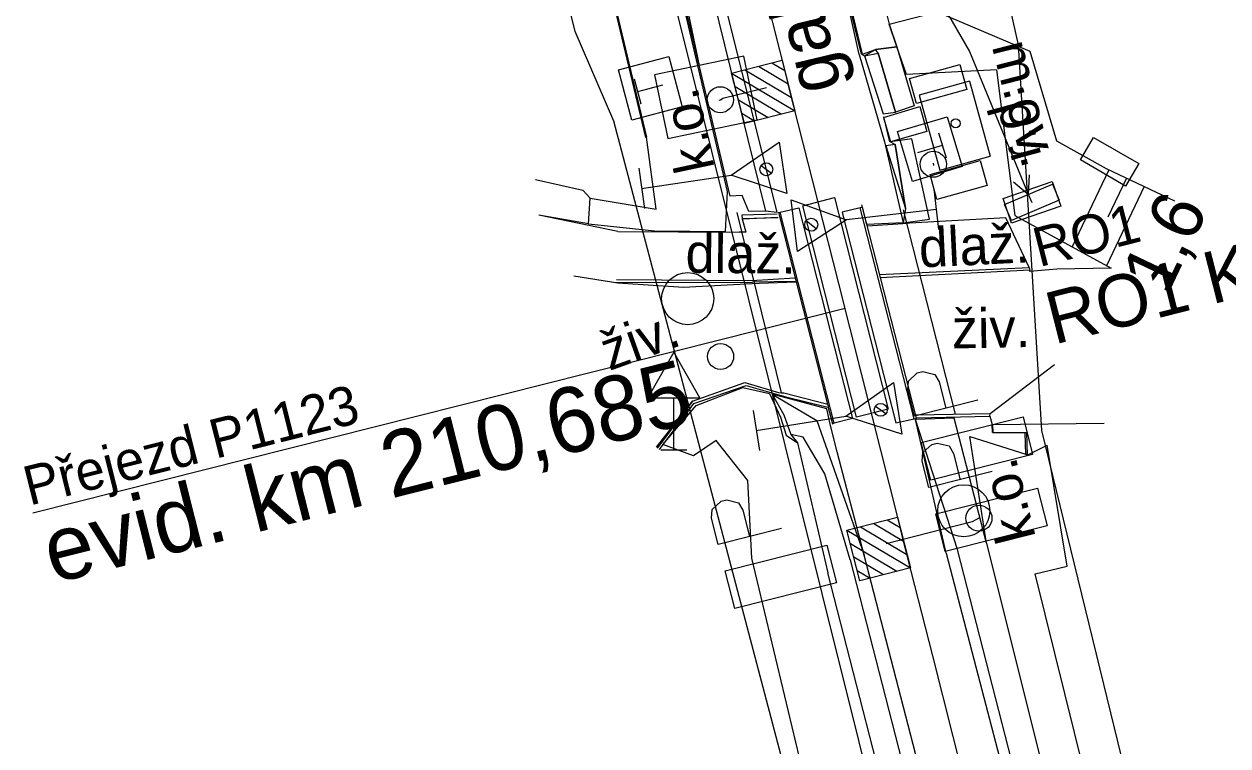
# Model space of a CAD drawing. Extents: x -754679 to -754173, y -1169241 to -1168288.
# Drawn here: x -754417.2 to -754371, y -1168972.24 to -1168944.54 of the extents above; entities that cross this region are included whole.
import ezdxf

# ---------------------------------------------------------------- set-up
doc = ezdxf.new("R2010")
doc.units = 0
for name, color, linetype in [('Vrstva 1', 7, 'Continuous'), ('Vrstva 13', 7, 'Continuous'), ('Vrstva 16', 7, 'Continuous'), ('Vrstva 23', 7, 'Continuous'), ('Vrstva 25', 7, 'Continuous'), ('Vrstva 27', 7, 'Continuous'), ('Vrstva 3', 7, 'Continuous'), ('Vrstva 31', 7, 'Continuous'), ('Vrstva 33', 7, 'Continuous'), ('Vrstva 37', 7, 'Continuous'), ('Vrstva 4', 7, 'Continuous'), ('Vrstva 43', 7, 'Continuous'), ('Vrstva 48', 7, 'Continuous'), ('Vrstva 49', 7, 'Continuous'), ('Vrstva 51', 7, 'Continuous'), ('Vrstva 53', 7, 'Continuous'), ('Vrstva 59', 7, 'Continuous'), ('Vrstva 63', 7, 'Continuous'), ('Vrstva 7', 7, 'Continuous')]:
    doc.layers.add(name, color=color, linetype=linetype)

msp = doc.modelspace()

# ---------------------------------------------------------------- linework, layer by layer
at = {"layer": 'Vrstva 1'}
for points in [[(-754384.656, -1168959.571), (-754385.936, -1168954.491), (-754386.734, -1168951.322), (-754387.865, -1168946.893), (-754387.928, -1168946.598), (-754389.016, -1168942.293), (-754391.2, -1168933.67), (-754393.647, -1168923.979), (-754396.084, -1168914.315), (-754398.294, -1168905.574)], [(-754382.327, -1168968.778), (-754383.436, -1168964.432), (-754383.656, -1168963.522), (-754384.656, -1168959.571)], [(-754371.756, -1169010.617), (-754373.805, -1169002.503), (-754376.012, -1168993.767), (-754377.617, -1168987.413), (-754379.98, -1168978.062), (-754382.327, -1168968.778)]]:
    msp.add_lwpolyline(points, dxfattribs=at)
at = {"layer": 'Vrstva 13'}
for p, q in [((-754385.032, -1168945.69), (-754385.963, -1168941.8)), ((-754384.759, -1168941.493), (-754384.006, -1168944.538)), ((-754385.064, -1168945.684), (-754386.023, -1168941.847)), ((-754385.032, -1168945.69), (-754384.522, -1168945.516)), ((-754385.064, -1168945.684), (-754385.032, -1168945.69)), ((-754375.751, -1168959.859), (-754380.036, -1168959.915)), ((-754380.025, -1168960.213), (-754378.726, -1168960.213)), ((-754378.753, -1168961.045), (-754378.786, -1168960.228)), ((-754378.726, -1168960.213), (-754378.701, -1168961.079)), ((-754378.701, -1168961.079), (-754378.753, -1168961.045))]:
    msp.add_line(p, q, dxfattribs=at)
for points in [[(-754384.006, -1168944.538), (-754383.71, -1168945.407), (-754384.522, -1168945.516)], [(-754385.064, -1168945.684), (-754384.955, -1168945.759), (-754384.522, -1168945.516)], [(-754378.726, -1168960.213), (-754378.786, -1168960.228), (-754380.038, -1168960.207), (-754380.043, -1168959.901), (-754380.036, -1168959.915)], [(-754380.036, -1168959.915), (-754380.025, -1168960.213), (-754380.038, -1168960.207)]]:
    msp.add_lwpolyline(points, dxfattribs=at)
at = {"layer": 'Vrstva 16'}
for p, q in [((-754390.209, -1168950.962), (-754395.222, -1168929.578)), ((-754397.82, -1168929.888), (-754393.322, -1168948.872)), ((-754384.955, -1168945.759), (-754384.428, -1168945.654)), ((-754384.428, -1168945.654), (-754383.763, -1168947.919)), ((-754395.546, -1168952.201), (-754395.477, -1168951.215)), ((-754391.51, -1168961.104), (-754392.688, -1168960.67)), ((-754377.17, -1168965.333), (-754377.937, -1168960.698)), ((-754380.262, -1168964.46), (-754374.593, -1168987.21)), ((-754383.092, -1168990.79), (-754389.273, -1168965.032)), ((-754378.402, -1168965.63), (-754377.17, -1168965.333)), ((-754380.395, -1168988.747), (-754386.358, -1168965.597)), ((-754373.145, -1168986.727), (-754378.402, -1168965.63))]:
    msp.add_line(p, q, dxfattribs=at)
for points in [[(-754384.955, -1168945.759), (-754384.237, -1168947.982), (-754383.763, -1168947.919)], [(-754395.477, -1168951.215), (-754392.947, -1168951.633), (-754393.322, -1168948.872)], [(-754383.768, -1168949.156), (-754384.136, -1168949.206), (-754383.375, -1168951.611), (-754383.768, -1168949.156)], [(-754395.546, -1168952.201), (-754393.01, -1168952.466), (-754390.289, -1168952.493), (-754390.209, -1168950.962)], [(-754392.688, -1168960.67), (-754391.408, -1168959.175), (-754389.621, -1168958.478), (-754388.593, -1168958.711), (-754388.173, -1168959.62), (-754387.958, -1168960.306), (-754387.518, -1168960.602), (-754386.358, -1168965.597)], [(-754389.273, -1168965.032), (-754389.425, -1168962.053), (-754390.641, -1168960.512), (-754391.51, -1168961.104)], [(-754380.262, -1168964.46), (-754380.906, -1168960.36), (-754378.753, -1168961.045), (-754378.701, -1168961.079), (-754377.937, -1168960.698)]]:
    msp.add_lwpolyline(points, dxfattribs=at)
at = {"layer": 'Vrstva 23'}
for p, q in [((-754380.917, -1168946.723), (-754382.852, -1168947.261)), ((-754380.917, -1168946.723), (-754380.127, -1168949.604)), ((-754382.852, -1168947.261), (-754382.062, -1168950.142)), ((-754384.221, -1168948.119), (-754382.823, -1168947.697)), ((-754382.062, -1168950.142), (-754380.127, -1168949.604))]:
    msp.add_line(p, q, dxfattribs=at)
for points in [[(-754393.344, -1168948.888), (-754397.546, -1168931.205), (-754401.742, -1168913.695), (-754408.583, -1168884.482)], [(-754382.823, -1168947.697), (-754382.557, -1168948.653), (-754383.948, -1168949.058), (-754383.977, -1168949.056), (-754384.212, -1168948.093), (-754384.221, -1168948.119), (-754383.948, -1168949.058)]]:
    msp.add_lwpolyline(points, dxfattribs=at)
at = {"layer": 'Vrstva 25'}
for points in [[(-754385.337, -1168937.932), (-754380.924, -1168945.594), (-754378.67, -1168951.057), (-754378.525, -1168951.376)], [(-754381.29, -1168946.084), (-754381.023, -1168947.048), (-754382.95, -1168947.584), (-754383.217, -1168946.62), (-754381.29, -1168946.084)], [(-754376.658, -1168949.746), (-754376.155, -1168948.882), (-754374.426, -1168949.888), (-754374.929, -1168950.752), (-754376.658, -1168949.746)], [(-754382.167, -1168951.272), (-754382.434, -1168950.308), (-754380.507, -1168949.772), (-754380.24, -1168950.736), (-754382.167, -1168951.272)], [(-754379.308, -1168952.174), (-754379.633, -1168951.228), (-754377.742, -1168950.578), (-754377.417, -1168951.524), (-754379.308, -1168952.174)]]:
    msp.add_lwpolyline(points, dxfattribs=at)
at = {"layer": 'Vrstva 27'}
for p, q in [((-754390.53, -1168947.452), (-754390.434, -1168947.426)), ((-754382.319, -1168949.867), (-754382.295, -1168949.963)), ((-754380.605, -1168963.514), (-754380.511, -1168963.48))]:
    msp.add_line(p, q, dxfattribs=at)
for points in [[(-754390.482, -1168947.439), (-754390.388, -1168947.376), (-754388.713, -1168946.964)], [(-754380.558, -1168963.497), (-754380.816, -1168963.643), (-754384.119, -1168964.483)]]:
    msp.add_lwpolyline(points, dxfattribs=at)
for centre in [(-754390.482, -1168947.439), (-754382.307, -1168949.915), (-754380.558, -1168963.497)]:
    msp.add_circle(centre, 0.5, dxfattribs=at)
at = {"layer": 'Vrstva 3'}
for p, q in [((-754390.05, -1168946.419), (-754387.618, -1168947.862)), ((-754389.537, -1168946.288), (-754387.749, -1168947.348)), ((-754389.022, -1168946.156), (-754387.88, -1168946.834)), ((-754388.509, -1168946.025), (-754388.011, -1168946.32)), ((-754389.919, -1168946.932), (-754388.131, -1168947.993)), ((-754389.788, -1168947.447), (-754388.646, -1168948.124)), ((-754389.657, -1168947.96), (-754389.159, -1168948.256)), ((-754385.621, -1168963.958), (-754383.189, -1168965.401)), ((-754385.108, -1168963.827), (-754383.32, -1168964.887)), ((-754384.593, -1168963.695), (-754383.451, -1168964.373)), ((-754384.08, -1168963.564), (-754383.582, -1168963.859)), ((-754385.49, -1168964.471), (-754383.702, -1168965.532)), ((-754385.359, -1168964.986), (-754384.217, -1168965.663)), ((-754385.228, -1168965.499), (-754384.73, -1168965.794))]:
    msp.add_line(p, q, dxfattribs=at)
for points in [[(-754388.112, -1168945.924), (-754387.618, -1168947.862), (-754389.555, -1168948.357), (-754390.05, -1168946.419)], [(-754383.683, -1168963.463), (-754383.189, -1168965.401), (-754385.127, -1168965.895), (-754385.621, -1168963.958)]]:
    msp.add_lwpolyline(points, close=True, dxfattribs=at)
at = {"layer": 'Vrstva 31'}
msp.add_lwpolyline([(-754388.719, -1168923.201), (-754385.337, -1168937.932), (-754380.924, -1168945.594), (-754378.67, -1168951.057), (-754378.525, -1168951.376)], dxfattribs=at)
at = {"layer": 'Vrstva 33'}
for p, q in [((-754393.523, -1168947.612), (-754393.778, -1168946.645)), ((-754393.65, -1168947.129), (-754392.684, -1168946.873)), ((-754382.106, -1168948.711), (-754381.818, -1168949.669)), ((-754381.962, -1168949.19), (-754382.92, -1168949.478)), ((-754379.573, -1168951.471), (-754379.569, -1168951.463))]:
    msp.add_line(p, q, dxfattribs=at)
for points in [[(-754393.879, -1168948.223), (-754394.389, -1168946.289), (-754392.455, -1168945.779), (-754391.945, -1168947.713), (-754393.879, -1168948.223)], [(-754381.771, -1168948.089), (-754381.196, -1168950.004), (-754383.111, -1168950.579), (-754383.686, -1168948.664), (-754381.771, -1168948.089)], [(-754379.227, -1168950.589), (-754378.657, -1168951.07), (-754378.614, -1168950.326)], [(-754383.287, -1168958.57), (-754383.262, -1168958.238), (-754382.923, -1168957.924), (-754382.708, -1168957.87), (-754382.251, -1168957.983), (-754382.087, -1168958.267)], [(-754382.087, -1168958.267), (-754381.832, -1168959.278)], [(-754383.032, -1168959.581), (-754383.287, -1168958.57)], [(-754380.6, -1168958.968), (-754383.032, -1168959.581)], [(-754382.732, -1168961.313), (-754382.708, -1168960.981), (-754382.368, -1168960.667), (-754382.154, -1168960.613), (-754381.697, -1168960.726), (-754381.532, -1168961.01)], [(-754381.532, -1168961.01), (-754381.277, -1168962.021)], [(-754382.477, -1168962.324), (-754382.732, -1168961.313)], [(-754380.045, -1168961.71), (-754382.477, -1168962.324)], [(-754390.816, -1168963.496), (-754390.792, -1168963.164), (-754390.452, -1168962.85), (-754390.238, -1168962.796), (-754389.781, -1168962.909), (-754389.616, -1168963.193)], [(-754390.561, -1168964.507), (-754390.816, -1168963.496)], [(-754389.616, -1168963.193), (-754389.361, -1168964.204)], [(-754388.129, -1168963.893), (-754390.561, -1168964.507)]]:
    msp.add_lwpolyline(points, dxfattribs=at)
for points in [[(-754379.575, -1168951.465), (-754377.738, -1168950.674), (-754377.475, -1168951.287), (-754379.312, -1168952.078)], [(-754382.404, -1168962.035), (-754382.768, -1168960.591), (-754378.861, -1168959.607), (-754378.498, -1168961.051)], [(-754381.848, -1168964.778), (-754382.212, -1168963.334), (-754378.306, -1168962.348), (-754377.941, -1168963.791)], [(-754389.932, -1168966.961), (-754390.296, -1168965.517), (-754386.39, -1168964.531), (-754386.025, -1168965.974)]]:
    msp.add_lwpolyline(points, close=True, dxfattribs=at)
at = {"layer": 'Vrstva 37'}
msp.add_circle((-754390.471, -1168957.291), 0.5, dxfattribs=at)
at = {"layer": 'Vrstva 4'}
for p, q in [((-754395.222, -1168929.578), (-754390.121, -1168951.135)), ((-754394.179, -1168929.708), (-754388.744, -1168951.72)), ((-754388.295, -1168951.767), (-754393.809, -1168929.698)), ((-754385.154, -1168945.699), (-754386.014, -1168941.847)), ((-754385.154, -1168945.699), (-754384.183, -1168949.051)), ((-754393.613, -1168950.071), (-754393.391, -1168951.611)), ((-754388.912, -1168949.959), (-754388.521, -1168950.254)), ((-754382.102, -1168952.423), (-754382.276, -1168950.877)), ((-754388.744, -1168951.72), (-754389.386, -1168951.727)), ((-754388.295, -1168951.767), (-754388.744, -1168951.72)), ((-754388.251, -1168951.769), (-754388.18, -1168951.751)), ((-754386.804, -1168952.39), (-754387.185, -1168952.083)), ((-754385.695, -1168955.447), (-754416.868, -1168963.298)), ((-754386.398, -1168959.295), (-754388.488, -1168958.734)), ((-754388.488, -1168958.734), (-754388.043, -1168959.526)), ((-754389.221, -1168959.358), (-754388.983, -1168960.896)), ((-754384.522, -1168959.194), (-754384.128, -1168959.484)), ((-754388.043, -1168959.526), (-754387.779, -1168960.28)), ((-754383.049, -1168959.681), (-754382.957, -1168959.657)), ((-754381.503, -1168959.659), (-754382.994, -1168959.713)), ((-754381.376, -1168964.701), (-754382.994, -1168959.713)), ((-754381.816, -1168964.835), (-754382.994, -1168959.713)), ((-754380.262, -1168964.46), (-754381.503, -1168959.659)), ((-754386.178, -1168959.871), (-754386.113, -1168959.854)), ((-754384.968, -1168964.915), (-754385.997, -1168960.947)), ((-754385.501, -1168965.091), (-754386.471, -1168961.789)), ((-754380.262, -1168964.46), (-754374.593, -1168987.21)), ((-754378.902, -1168988.336), (-754384.968, -1168964.915)), ((-754381.816, -1168964.835), (-754375.862, -1168987.584)), ((-754375.554, -1168987.357), (-754381.376, -1168964.701)), ((-754385.501, -1168965.091), (-754379.508, -1168988.473)), ((-754380.395, -1168988.747), (-754386.358, -1168965.597))]:
    msp.add_line(p, q, dxfattribs=at)
for points in [[(-754383.71, -1168945.407), (-754383.049, -1168947.673), (-754383.763, -1168947.919), (-754384.428, -1168945.654), (-754384.522, -1168945.516), (-754383.71, -1168945.407)], [(-754393.502, -1168950.841), (-754390.062, -1168950.335), (-754388.221, -1168949.067), (-754387.924, -1168951.043), (-754390.062, -1168950.335)], [(-754384.183, -1168949.051), (-754383.468, -1168952.159), (-754384.853, -1168952.232), (-754385.049, -1168951.469)], [(-754383.468, -1168952.159), (-754382.456, -1168952.028), (-754383.132, -1168948.942), (-754383.948, -1168949.058), (-754383.768, -1168949.156), (-754383.375, -1168951.611), (-754383.468, -1168952.159)], [(-754389.386, -1168951.727), (-754389.648, -1168951.116), (-754390.121, -1168951.135)], [(-754382.189, -1168951.65), (-754385.643, -1168952.05), (-754387.522, -1168953.26), (-754387.758, -1168951.276), (-754385.643, -1168952.05)], [(-754384.042, -1168959.317), (-754385.257, -1168959.617), (-754387.319, -1168951.515), (-754386.094, -1168951.188), (-754384.042, -1168959.317)], [(-754388.251, -1168951.769), (-754388.199, -1168951.972), (-754387.569, -1168954.421), (-754386.369, -1168959.123), (-754386.343, -1168959.225), (-754386.338, -1168959.246), (-754386.178, -1168959.871)], [(-754385.407, -1168959.668), (-754386.113, -1168959.854), (-754388.18, -1168951.751), (-754387.468, -1168951.586), (-754385.407, -1168959.668)], [(-754383.749, -1168959.835), (-754383.049, -1168959.681), (-754385.116, -1168951.584), (-754385.803, -1168951.759), (-754385.802, -1168951.762), (-754383.749, -1168959.835)], [(-754385.02, -1168951.56), (-754385.116, -1168951.584)], [(-754382.957, -1168959.657), (-754385.02, -1168951.56)], [(-754389.102, -1168960.127), (-754385.668, -1168959.583), (-754383.841, -1168958.294), (-754383.522, -1168960.267), (-754385.668, -1168959.583)], [(-754388.488, -1168958.734), (-754386.775, -1168959.754), (-754384.968, -1168964.915)], [(-754385.997, -1168960.947), (-754386.261, -1168959.886), (-754386.398, -1168959.295)], [(-754386.471, -1168961.789), (-754387.297, -1168960.39), (-754387.779, -1168960.28)], [(-754387.779, -1168960.28), (-754387.518, -1168960.602), (-754386.358, -1168965.597)]]:
    msp.add_lwpolyline(points, dxfattribs=at)
for centre in [(-754388.718, -1168950.107), (-754386.994, -1168952.236), (-754384.326, -1168959.34)]:
    msp.add_circle(centre, 0.248, dxfattribs=at)
at = {"layer": 'Vrstva 43'}
for p, q in [((-754388.13, -1168958.682), (-754389.832, -1168951.766)), ((-754381.456, -1168959.502), (-754383.446, -1168951.67))]:
    msp.add_line(p, q, dxfattribs=at)
for centre in [(-754391.734, -1168955.072), (-754381.14, -1168963.213)]:
    msp.add_circle(centre, 1, dxfattribs=at)
at = {"layer": 'Vrstva 48'}
for p, q in [((-754375.576, -1168950.125), (-754376.982, -1168953.083)), ((-754374.899, -1168950.446), (-754375.611, -1168951.946)), ((-754374.221, -1168950.768), (-754375.666, -1168953.808))]:
    msp.add_line(p, q, dxfattribs=at)
at = {"layer": 'Vrstva 49'}
for points in [[(-754384.006, -1168944.538), (-754382.158, -1168944.067), (-754378.6, -1168945.58), (-754377.58, -1168949.01), (-754375.672, -1168950.079), (-754373.052, -1168951.324)], [(-754379.885, -1168946.291), (-754383.334, -1168946.469), (-754383.71, -1168945.407), (-754384.006, -1168944.538)], [(-754379.885, -1168946.291), (-754379.174, -1168951.877), (-754375.483, -1168953.908)], [(-754397.582, -1168950.504), (-754395.757, -1168950.913), (-754395.477, -1168951.215)], [(-754395.546, -1168952.201), (-754397.45, -1168951.868)]]:
    msp.add_lwpolyline(points, dxfattribs=at)
at = {"layer": 'Vrstva 51'}
for p, q in [((-754388.305, -1168951.83), (-754389.651, -1168951.864)), ((-754388.26, -1168951.97), (-754389.641, -1168952.015)), ((-754394.422, -1168952.497), (-754389.758, -1168952.527)), ((-754377.567, -1168953.938), (-754378.597, -1168954.036)), ((-754394.492, -1168954.446), (-754389.242, -1168954.445)), ((-754394.471, -1168954.337), (-754389.288, -1168954.378)), ((-754389.254, -1168954.492), (-754388.995, -1168954.482)), ((-754388.995, -1168954.482), (-754387.569, -1168954.421)), ((-754380.13, -1168959.479), (-754377.659, -1168957.604)), ((-754389.542, -1168958.287), (-754388.252, -1168958.676)), ((-754389.488, -1168958.402), (-754387.963, -1168958.835)), ((-754382.989, -1168959.532), (-754380.13, -1168959.479)), ((-754392.763, -1168960.875), (-754391.763, -1168960.875))]:
    msp.add_line(p, q, dxfattribs=at)
for points in [[(-754394.422, -1168952.497), (-754397.45, -1168951.868)], [(-754389.651, -1168951.864), (-754389.641, -1168952.008), (-754389.641, -1168952.015), (-754389.509, -1168952.517), (-754389.758, -1168952.527)], [(-754389.641, -1168952.008), (-754389.633, -1168952.008), (-754388.281, -1168951.95)], [(-754378.633, -1168953.874), (-754379.525, -1168951.969), (-754383.21, -1168952.179), (-754383.477, -1168952.204), (-754384.839, -1168952.296)], [(-754396.105, -1168954.199), (-754394.412, -1168954.467)], [(-754389.288, -1168954.378), (-754387.625, -1168954.272), (-754387.608, -1168954.271)], [(-754384.382, -1168954.15), (-754378.633, -1168953.874), (-754378.608, -1168953.978)], [(-754378.597, -1168954.036), (-754378.608, -1168953.978), (-754384.364, -1168954.276)], [(-754375.483, -1168953.908), (-754377.567, -1168953.938)], [(-754394.412, -1168954.467), (-754391.899, -1168954.63), (-754389.254, -1168954.492)], [(-754387.571, -1168954.415), (-754387.591, -1168954.415), (-754389.242, -1168954.445)], [(-754392.263, -1168960.875), (-754392.263, -1168958.875), (-754391.263, -1168958.875), (-754392.263, -1168957.125), (-754393.263, -1168958.875), (-754392.263, -1168958.875)], [(-754392.928, -1168960.766), (-754391.546, -1168959.003), (-754389.542, -1168958.287)], [(-754392.821, -1168960.856), (-754391.495, -1168959.096), (-754389.488, -1168958.402)], [(-754388.252, -1168958.676), (-754388.13, -1168958.682), (-754388.047, -1168958.683)], [(-754388.047, -1168958.683), (-754386.411, -1168959.112), (-754386.369, -1168959.123)], [(-754387.963, -1168958.835), (-754386.358, -1168959.241), (-754386.338, -1168959.246)], [(-754392.891, -1168960.815), (-754391.532, -1168959.012), (-754391.546, -1168959.003)], [(-754382.96, -1168959.646), (-754382.937, -1168959.645), (-754380.136, -1168959.582), (-754380.13, -1168959.479)], [(-754380.136, -1168959.582), (-754380.043, -1168959.901)]]:
    msp.add_lwpolyline(points, dxfattribs=at)
at = {"layer": 'Vrstva 53'}
for p, q in [((-754396.56, -1168868.29), (-754379.05, -1168945.33)), ((-754396.05, -1168944.82), (-754406.43, -1168903.09)), ((-754394.57, -1168948.26), (-754396.05, -1168944.82)), ((-754379.05, -1168945.33), (-754378.16, -1168960.13)), ((-754378.16, -1168960.13), (-754373.54, -1168979.01))]:
    msp.add_line(p, q, dxfattribs=at)
msp.add_lwpolyline([(-754345.91, -1169130.8), (-754386.06, -1168980.52), (-754394.57, -1168948.26)], dxfattribs=at)
at = {"layer": 'Vrstva 59'}
msp.add_circle((-754381.446, -1168948.347), 0.175, dxfattribs=at)
at = {"layer": 'Vrstva 63'}
msp.add_lwpolyline([(-754409.148, -1168875.914), (-754380.947, -1168989.007), (-754335.988, -1169164.84)], dxfattribs=at)
at = {"layer": 'Vrstva 7'}
msp.add_lwpolyline([(-754391.909, -1168943.185), (-754391.296, -1168946.122), (-754393.009, -1168946.479), (-754392.499, -1168948.927), (-754389.072, -1168948.212), (-754389.583, -1168945.764), (-754391.296, -1168946.122)], dxfattribs=at)

# ---------------------------------------------------------------- texts
at = {"layer": 'Vrstva 13'}
msp.add_text('gabion', height=2, rotation=103.4595, dxfattribs=at).set_placement((-754385.81, -1168946.939))
at = {"layer": 'Vrstva 23'}
msp.add_text('r.d.', height=1.5, rotation=105.3342, dxfattribs=at).set_placement((-754378.146, -1168949.583))
at = {"layer": 'Vrstva 25'}
msp.add_text('RO1', height=1.5, rotation=14.2781, dxfattribs=at).set_placement((-754378.247, -1168953.868))
at = {"layer": 'Vrstva 27'}
for s, rotation, p in [('m.ov.', 284.325, (-754380.069, -1168945.381)), ('k.o.', 102.055, (-754390.696, -1168950.059)), ('k.o.', 104.2033, (-754378.367, -1168964.226))]:
    msp.add_text(s, height=1.5, rotation=rotation, dxfattribs=at).set_placement(p)
at = {"layer": 'Vrstva 33'}
msp.add_text('RO1 KS1 KF1', height=2, rotation=14.2781, dxfattribs=at).set_placement((-754377.672, -1168956.84))
at = {"layer": 'Vrstva 4'}
for s, height, p in [('evid. km 210,685', 2.5, (-754416.099, -1168966.015)), ('Přejezd P1123', 1.5, (-754416.998, -1168963.018))]:
    msp.add_text(s, height=height, rotation=14.136, dxfattribs=at).set_placement(p)
at = {"layer": 'Vrstva 48'}
msp.add_text('1,6', height=2, rotation=64.5834, dxfattribs=at).set_placement((-754373.34, -1168955.003))
at = {"layer": 'Vrstva 51'}
for s, rotation, p in [('dlaž.', 2.7486, (-754382.827, -1168953.878)), ('dlaž.', 359.5468, (-754391.822, -1168954.076)), ('živ.', 1.062, (-754381.587, -1168956.984)), ('živ.', 19.6611, (-754394.745, -1168957.851))]:
    msp.add_text(s, height=1.5, rotation=rotation, dxfattribs=at).set_placement(p)

doc.saveas('drawing.dxf')
